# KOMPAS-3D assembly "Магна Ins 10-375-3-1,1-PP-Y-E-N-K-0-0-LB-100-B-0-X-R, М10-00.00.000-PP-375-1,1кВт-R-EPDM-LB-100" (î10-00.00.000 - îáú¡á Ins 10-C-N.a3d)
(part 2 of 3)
- Part/product: Магна Ins 10-425-3-1,1-PP-Y-E-N-K-0-0-L-0-B-0-X-M  | designation М10-00.00.000-PP-425-1,1кВт-M-EPDM
    Материал: Полипропилен  ГОСТ 26996-86 (density 900 kg/m3)
    Масса: 15.9855
  - Component [assembly]: Корпус полипропилен 425 1,1кВт  / с разъёмной муфтой  | designation М10-00.20.000-PP-425-1,1кВт-M  | pos. 2  | Материал: Полипропилен  ГОСТ 26996-86 (density 900 kg/m3); Масса: 5.90542; Раздел спецификации: Сборочные единицы; Форматы листов документа: 3xA3; Примечание: @100~)3xA3@101~)3xA3
  - Component [detail]: Электродвигатель / АИР 71B2 IM 3081 IP55 ф."Элком"  | pos. 14  | Масса: 8.3; Раздел спецификации: Прочие изделия; Примечание: См. заказ
  - Component [assembly]: Вал  | designation М10-00.15.000-1,1кВт-425  | pos. 1
      Материал: Полипропилен  ГОСТ 26996-86 (density 900 kg/m3)
      Масса: 0.906297
      Раздел спецификации: Сборочные единицы
      Форматы листов документа: 2xA3
      Примечание: @100~)2xA3
      source file: М10-00.15.000 - Вал.a3d
  - Component [detail]: Крышка  | designation М10-00.00.002  | pos. 4
      Материал: Полипропилен  ГОСТ 26996-86 (density 900 kg/m3)
      Масса: 0.324102
      Раздел спецификации: Детали
      Форматы листов документа: 4xA4
      Примечание: @100~)4xA4
      source file: М10-00.00.002 - Крышка.cdw, М10-00.00.002 - Крышка.m3d
  - Component [detail]: Импеллер Магна10  | designation М10-00.00.001  | pos. 3  | Масса: 0.169927; Раздел спецификации: Детали; Форматы листов документа: A3; source file: М10-00.00.001 - Импеллер Магна10.cdw, М10-00.00.001 - Импеллер Магна10.m3d
  - Component [detail]: Защитная втулка  | designation М10-00.00.003  | pos. 5  | Масса: 0.0193569; Раздел спецификации: Детали; Форматы листов документа: A4; source file: D:\Magna\Магна Ins\Магна ins 10\М10-00.00.000\3Д\М10-00.00.003 - Защитная втулка.cdw, М10-00.00.003 - Защитная втулка.m3d
  - Component [detail]: Втулка ответная  | designation М10А-00.00.003-01  | pos. 6  | Масса: 0.031838; Раздел спецификации: Детали; Форматы листов документа: A4; Примечание: Заим.; source file: D:\AquaProf\АкваProf 190\3Д модель\..\..\..\Magna\Магна Ins\Магна ins 10\М10-00.00.000\3Д\М10А-00.00.003-01 - Втулка ответная.cdw, D:\AquaProf\АкваProf 190\3Д модель\М10А-00.00.003 - Втулка ответная.m3d
  - Component [standard]: Шайба C.10.21 ГОСТ 11371-78  | qty 4  | pos. 11  | Материал: Сталь 12Х18Н10Т ГОСТ 5632-72 (density 1000 kg/m3); Масса: 0.003438; Раздел спецификации: Стандартные изделия; additional columns: C.8.21; Сталь 12Х18Н10Т ГОСТ 5632-72
  - Component [standard]: Шайба C.10.21 ГОСТ 11371-78  | qty 4  | pos. 11  | Материал: Сталь 12Х18Н10Т ГОСТ 5632-72 (density 1000 kg/m3); Масса: 0.003438; Раздел спецификации: Стандартные изделия; Рассекать на разрезах: no; additional columns: Сталь 12Х18Н10Т ГОСТ 5632-72
  - Component [standard]: Шайба 10 ГОСТ 6402-70  | qty 4  | pos. 10  | Масса: 0.00201; Раздел спецификации: Стандартные изделия; Примечание: Нерж.; Рассекать на разрезах: no; additional columns: 10; Без указания материала
  - Component [standard]: Гайка М10x1,25-6H(S16) ГОСТ 5915-70  | qty 4  | pos. 9  | Масса: 0.01022; Раздел спецификации: Стандартные изделия; Рассекать на разрезах: no; additional columns: М10x1,25-6H (S16); Сталь 12Х18Н10Т ГОСТ 5632-72
  - Component [standard]: Болт М10-6gx60.21.12Х18Н10Т ГОСТ 7798-70  | qty 4  | pos. 8  | Масса: 0.0467; Раздел спецификации: Стандартные изделия; additional columns: М8-6gx55.21.12Х18Н10Т; Сталь 12Х18Н10Т ГОСТ 5632-72
  - Component [detail]: Заглушка @2~25 FV PPR ф. "FV-Plast"  | qty 4  | pos. 12  | Материал: Полипропилен  ГОСТ 26996-86 (density 900 kg/m3); Масса: 0.0161976; Раздел спецификации: Прочие изделия
- Part/product: Магна Ins 10-425-3-0,75-PP-Y-E-N-K-0-0-L-0-B-0-X-R  | designation М10-00.00.000-PP-425-0,75кВт-R-EPDM
    Материал: Полипропилен  ГОСТ 26996-86 (density 900 kg/m3)
    Масса: 15.0715
  - Component [assembly]: Корпус полипропилен 425 0,75кВт  / с резьбовым переходником  | designation М10-00.20.000-PP-425-0,75кВт-R  | pos. 2  | Материал: Полипропилен  ГОСТ 26996-86 (density 900 kg/m3); Масса: 4.98891; Раздел спецификации: Сборочные единицы; Форматы листов документа: 3xA3; Примечание: @100~)3xA3@101~)3xA3
  - Component [assembly]: Вал  | designation М10-00.15.000-0,75кВт-425  | pos. 1
      Материал: Полипропилен  ГОСТ 26996-86 (density 900 kg/m3)
      Масса: 0.908797
      Раздел спецификации: Сборочные единицы
      Форматы листов документа: 2xA3
      Примечание: @100~)2xA3
      source file: М10-00.15.000 - Вал.a3d
  - Component [detail]: Крышка  | designation М10-00.00.002  | pos. 4
      Материал: Полипропилен  ГОСТ 26996-86 (density 900 kg/m3)
      Масса: 0.324102
      Раздел спецификации: Детали
      Форматы листов документа: 4xA4
      Примечание: @100~)4xA4
      source file: М10-00.00.002 - Крышка.cdw, М10-00.00.002 - Крышка.m3d
  - Component [detail]: Импеллер Магна10  | designation М10-00.00.001  | pos. 3  | Масса: 0.169927; Раздел спецификации: Детали; Форматы листов документа: A3; source file: М10-00.00.001 - Импеллер Магна10.cdw, М10-00.00.001 - Импеллер Магна10.m3d
  - Component [detail]: Защитная втулка  | designation М10-00.00.003  | pos. 5  | Масса: 0.0193569; Раздел спецификации: Детали; Форматы листов документа: A4; source file: D:\Magna\Магна Ins\Магна ins 10\М10-00.00.000\3Д\М10-00.00.003 - Защитная втулка.cdw, М10-00.00.003 - Защитная втулка.m3d
  - Component [detail]: Втулка ответная  | designation М10А-00.00.003-01  | pos. 6  | Масса: 0.031838; Раздел спецификации: Детали; Форматы листов документа: A4; Примечание: Заим.; source file: D:\AquaProf\АкваProf 190\3Д модель\..\..\..\Magna\Магна Ins\Магна ins 10\М10-00.00.000\3Д\М10А-00.00.003-01 - Втулка ответная.cdw, D:\AquaProf\АкваProf 190\3Д модель\М10А-00.00.003 - Втулка ответная.m3d
  - Component [standard]: Шайба C.10.21 ГОСТ 11371-78  | qty 4  | pos. 11  | Материал: Сталь 12Х18Н10Т ГОСТ 5632-72 (density 1000 kg/m3); Масса: 0.003438; Раздел спецификации: Стандартные изделия; additional columns: C.8.21; Сталь 12Х18Н10Т ГОСТ 5632-72
  - Component [standard]: Шайба C.10.21 ГОСТ 11371-78  | qty 4  | pos. 11  | Материал: Сталь 12Х18Н10Т ГОСТ 5632-72 (density 1000 kg/m3); Масса: 0.003438; Раздел спецификации: Стандартные изделия; Рассекать на разрезах: no; additional columns: Сталь 12Х18Н10Т ГОСТ 5632-72
  - Component [standard]: Шайба 10 ГОСТ 6402-70  | qty 4  | pos. 10  | Масса: 0.00201; Раздел спецификации: Стандартные изделия; Примечание: Нерж.; Рассекать на разрезах: no; additional columns: 10; Без указания материала
  - Component [standard]: Гайка М10x1,25-6H(S16) ГОСТ 5915-70  | qty 4  | pos. 9  | Масса: 0.01022; Раздел спецификации: Стандартные изделия; Рассекать на разрезах: no; additional columns: М10x1,25-6H (S16); Сталь 12Х18Н10Т ГОСТ 5632-72
  - Component [standard]: Болт М10-6gx60.21.12Х18Н10Т ГОСТ 7798-70  | qty 4  | pos. 8  | Масса: 0.0467; Раздел спецификации: Стандартные изделия; additional columns: М8-6gx55.21.12Х18Н10Т; Сталь 12Х18Н10Т ГОСТ 5632-72
  - Component [detail]: Заглушка @2~25 FV PPR ф. "FV-Plast"  | qty 4  | pos. 12  | Материал: Полипропилен  ГОСТ 26996-86 (density 900 kg/m3); Масса: 0.0161976; Раздел спецификации: Прочие изделия
- Part/product: Магна Ins 10-425-3-0,75-PP-Y-E-N-K-0-0-L-0-B-0-X-M  | designation М10-00.00.000-PP-425-0,75кВт-M-EPDM
    Материал: Полипропилен  ГОСТ 26996-86 (density 900 kg/m3)
    Масса: 15.988
  - Component [assembly]: Корпус полипропилен 425 0,75кВт  / с разъёмной муфтой  | designation М10-00.20.000-PP-425-0,75кВт-M  | pos. 2  | Материал: Полипропилен  ГОСТ 26996-86 (density 900 kg/m3); Масса: 5.90542; Раздел спецификации: Сборочные единицы; Форматы листов документа: 3xA3; Примечание: @100~)3xA3@101~)3xA3
  - Component [assembly]: Вал  | designation М10-00.15.000-0,75кВт-425  | pos. 1
      Материал: Полипропилен  ГОСТ 26996-86 (density 900 kg/m3)
      Масса: 0.908797
      Раздел спецификации: Сборочные единицы
      Форматы листов документа: 2xA3
      Примечание: @100~)2xA3
      source file: М10-00.15.000 - Вал.a3d
  - Component [detail]: Крышка  | designation М10-00.00.002  | pos. 4
      Материал: Полипропилен  ГОСТ 26996-86 (density 900 kg/m3)
      Масса: 0.324102
      Раздел спецификации: Детали
      Форматы листов документа: 4xA4
      Примечание: @100~)4xA4
      source file: М10-00.00.002 - Крышка.cdw, М10-00.00.002 - Крышка.m3d
  - Component [detail]: Импеллер Магна10  | designation М10-00.00.001  | pos. 3  | Масса: 0.169927; Раздел спецификации: Детали; Форматы листов документа: A3; source file: М10-00.00.001 - Импеллер Магна10.cdw, М10-00.00.001 - Импеллер Магна10.m3d
  - Component [detail]: Защитная втулка  | designation М10-00.00.003  | pos. 5  | Масса: 0.0193569; Раздел спецификации: Детали; Форматы листов документа: A4; source file: D:\Magna\Магна Ins\Магна ins 10\М10-00.00.000\3Д\М10-00.00.003 - Защитная втулка.cdw, М10-00.00.003 - Защитная втулка.m3d
  - Component [detail]: Втулка ответная  | designation М10А-00.00.003-01  | pos. 6  | Масса: 0.031838; Раздел спецификации: Детали; Форматы листов документа: A4; Примечание: Заим.; source file: D:\AquaProf\АкваProf 190\3Д модель\..\..\..\Magna\Магна Ins\Магна ins 10\М10-00.00.000\3Д\М10А-00.00.003-01 - Втулка ответная.cdw, D:\AquaProf\АкваProf 190\3Д модель\М10А-00.00.003 - Втулка ответная.m3d
  - Component [standard]: Шайба C.10.21 ГОСТ 11371-78  | qty 4  | pos. 11  | Материал: Сталь 12Х18Н10Т ГОСТ 5632-72 (density 1000 kg/m3); Масса: 0.003438; Раздел спецификации: Стандартные изделия; additional columns: C.8.21; Сталь 12Х18Н10Т ГОСТ 5632-72
  - Component [standard]: Шайба C.10.21 ГОСТ 11371-78  | qty 4  | pos. 11  | Материал: Сталь 12Х18Н10Т ГОСТ 5632-72 (density 1000 kg/m3); Масса: 0.003438; Раздел спецификации: Стандартные изделия; Рассекать на разрезах: no; additional columns: Сталь 12Х18Н10Т ГОСТ 5632-72
  - Component [standard]: Шайба 10 ГОСТ 6402-70  | qty 4  | pos. 10  | Масса: 0.00201; Раздел спецификации: Стандартные изделия; Примечание: Нерж.; Рассекать на разрезах: no; additional columns: 10; Без указания материала
  - Component [standard]: Гайка М10x1,25-6H(S16) ГОСТ 5915-70  | qty 4  | pos. 9  | Масса: 0.01022; Раздел спецификации: Стандартные изделия; Рассекать на разрезах: no; additional columns: М10x1,25-6H (S16); Сталь 12Х18Н10Т ГОСТ 5632-72
  - Component [standard]: Болт М10-6gx60.21.12Х18Н10Т ГОСТ 7798-70  | qty 4  | pos. 8  | Масса: 0.0467; Раздел спецификации: Стандартные изделия; additional columns: М8-6gx55.21.12Х18Н10Т; Сталь 12Х18Н10Т ГОСТ 5632-72
  - Component [detail]: Заглушка @2~25 FV PPR ф. "FV-Plast"  | qty 4  | pos. 12  | Материал: Полипропилен  ГОСТ 26996-86 (density 900 kg/m3); Масса: 0.0161976; Раздел спецификации: Прочие изделия
- Part/product: Магна Ins 10-PP-425-1,1кВт  | designation М10-00.00.000-PP-425-1,1кВт
    Материал: Полипропилен  ГОСТ 26996-86 (density 900 kg/m3)
    Масса: 15.0361
  - Component [detail]: Заглушка @2~25 FV PPR ф. "FV-Plast"  | qty 4  | pos. 12  | Материал: Полипропилен  ГОСТ 26996-86 (density 900 kg/m3); Масса: 0.0161976; Раздел спецификации: Прочие изделия
  - Component [standard]: Болт М10x1,25-6gx60 (S16) ГОСТ 7798-70  | qty 4  | pos. 8  | Масса: 0.0467; Раздел спецификации: Стандартные изделия; Рассекать на разрезах: no; additional columns: Сталь 12Х18Н10Т ГОСТ 5632-72
  - Component [standard]: Гайка М10x1,25-6H(S16) ГОСТ 5915-70  | qty 4  | pos. 9  | Масса: 0.01022; Раздел спецификации: Стандартные изделия; Рассекать на разрезах: no; additional columns: М10x1,25-6H (S16); Сталь 12Х18Н10Т ГОСТ 5632-72
  - Component [standard]: Шайба 10 ГОСТ 6402-70  | qty 4  | pos. 10  | Масса: 0.00201; Раздел спецификации: Стандартные изделия; Примечание: Нерж.; Рассекать на разрезах: no; additional columns: 10; Без указания материала
  - Component [standard]: Шайба C.10.21 ГОСТ 11371-78  | qty 8  | pos. 11  | Материал: Сталь 12Х18Н10Т ГОСТ 5632-72 (density 1000 kg/m3); Масса: 0.003438; Раздел спецификации: Стандартные изделия; Рассекать на разрезах: no; additional columns: Сталь 12Х18Н10Т ГОСТ 5632-72
  - Component [detail]: Втулка ответная  | designation М10А-00.00.003-01  | pos. 6  | Масса: 0.031838; Раздел спецификации: Детали; Форматы листов документа: A4; Примечание: Заим.; source file: D:\AquaProf\АкваProf 190\3Д модель\..\..\..\Magna\Магна Ins\Магна ins 10\М10-00.00.000\3Д\М10А-00.00.003-01 - Втулка ответная.cdw, D:\AquaProf\АкваProf 190\3Д модель\М10А-00.00.003 - Втулка ответная.m3d
  - Component [detail]: Защитная втулка  | designation М10-00.00.003  | pos. 5  | Масса: 0.0193569; Раздел спецификации: Детали; Форматы листов документа: A4; source file: D:\Magna\Магна Ins\Магна ins 10\М10-00.00.000\3Д\М10-00.00.003 - Защитная втулка.cdw, М10-00.00.003 - Защитная втулка.m3d
  - Component [detail]: Импеллер Магна10  | designation М10-00.00.001  | pos. 3  | Масса: 0.169927; Раздел спецификации: Детали; Форматы листов документа: A3; source file: М10-00.00.001 - Импеллер Магна10.cdw, М10-00.00.001 - Импеллер Магна10.m3d
  - Component [detail]: Крышка  | designation М10-00.00.002  | pos. 4
      Материал: Полипропилен  ГОСТ 26996-86 (density 900 kg/m3)
      Масса: 0.324102
      Раздел спецификации: Детали
      Форматы листов документа: 4xA4
      Примечание: @100~)4xA4
      source file: М10-00.00.002 - Крышка.cdw, М10-00.00.002 - Крышка.m3d
  - Component [assembly]: Вал  | designation М10-00.15.000-1,1кВт-425  | pos. 1
      Материал: Полипропилен  ГОСТ 26996-86 (density 900 kg/m3)
      Масса: 0.906297
      Раздел спецификации: Сборочные единицы
      Форматы листов документа: 2xA3
      Примечание: @100~)2xA3
      source file: М10-00.15.000 - Вал.a3d
  - Component [detail]: Электродвигатель / АИР 71B2 IM 3081 IP55 ф."Элком"  | pos. 14  | Масса: 8.3; Раздел спецификации: Прочие изделия; Примечание: См. заказ
  - Component [assembly]: Корпус полипропилен 425 1,1кВт  | designation М10-00.20.000-PP-425-1,1кВт  | pos. 2  | Материал: Полипропилен  ГОСТ 26996-86 (density 900 kg/m3); Масса: 4.95604; Раздел спецификации: Сборочные единицы; Форматы листов документа: 3xA3; Примечание: @100~)3xA3@101~)3xA3
- Part/product: Магна Ins 10-PP-425-0,75кВт  | designation М10-00.00.000-PP-425-0,75кВт
    Материал: Полипропилен  ГОСТ 26996-86 (density 900 kg/m3)
    Масса: 15.0386
  - Component [detail]: Заглушка @2~25 FV PPR ф. "FV-Plast"  | qty 4  | pos. 12  | Материал: Полипропилен  ГОСТ 26996-86 (density 900 kg/m3); Масса: 0.0161976; Раздел спецификации: Прочие изделия
  - Component [standard]: Болт М10x1,25-6gx60 (S16) ГОСТ 7798-70  | qty 4  | pos. 8  | Масса: 0.0467; Раздел спецификации: Стандартные изделия; Рассекать на разрезах: no; additional columns: Сталь 12Х18Н10Т ГОСТ 5632-72
  - Component [standard]: Гайка М10x1,25-6H(S16) ГОСТ 5915-70  | qty 4  | pos. 9  | Масса: 0.01022; Раздел спецификации: Стандартные изделия; Рассекать на разрезах: no; additional columns: М10x1,25-6H (S16); Сталь 12Х18Н10Т ГОСТ 5632-72
  - Component [standard]: Шайба 10 ГОСТ 6402-70  | qty 4  | pos. 10  | Масса: 0.00201; Раздел спецификации: Стандартные изделия; Примечание: Нерж.; Рассекать на разрезах: no; additional columns: 10; Без указания материала
  - Component [standard]: Шайба C.10.21 ГОСТ 11371-78  | qty 8  | pos. 11  | Материал: Сталь 12Х18Н10Т ГОСТ 5632-72 (density 1000 kg/m3); Масса: 0.003438; Раздел спецификации: Стандартные изделия; Рассекать на разрезах: no; additional columns: Сталь 12Х18Н10Т ГОСТ 5632-72
  - Component [detail]: Втулка ответная  | designation М10А-00.00.003-01  | pos. 6  | Масса: 0.031838; Раздел спецификации: Детали; Форматы листов документа: A4; Примечание: Заим.; source file: D:\AquaProf\АкваProf 190\3Д модель\..\..\..\Magna\Магна Ins\Магна ins 10\М10-00.00.000\3Д\М10А-00.00.003-01 - Втулка ответная.cdw, D:\AquaProf\АкваProf 190\3Д модель\М10А-00.00.003 - Втулка ответная.m3d
  - Component [detail]: Защитная втулка  | designation М10-00.00.003  | pos. 5  | Масса: 0.0193569; Раздел спецификации: Детали; Форматы листов документа: A4; source file: D:\Magna\Магна Ins\Магна ins 10\М10-00.00.000\3Д\М10-00.00.003 - Защитная втулка.cdw, М10-00.00.003 - Защитная втулка.m3d
  - Component [detail]: Импеллер Магна10  | designation М10-00.00.001  | pos. 3  | Масса: 0.169927; Раздел спецификации: Детали; Форматы листов документа: A3; source file: М10-00.00.001 - Импеллер Магна10.cdw, М10-00.00.001 - Импеллер Магна10.m3d
  - Component [detail]: Крышка  | designation М10-00.00.002  | pos. 4
      Материал: Полипропилен  ГОСТ 26996-86 (density 900 kg/m3)
      Масса: 0.324102
      Раздел спецификации: Детали
      Форматы листов документа: 4xA4
      Примечание: @100~)4xA4
      source file: М10-00.00.002 - Крышка.cdw, М10-00.00.002 - Крышка.m3d
  - Component [assembly]: Вал  | designation М10-00.15.000-0,75кВт-425  | pos. 1
      Материал: Полипропилен  ГОСТ 26996-86 (density 900 kg/m3)
      Масса: 0.908797
      Раздел спецификации: Сборочные единицы
      Форматы листов документа: 2xA3
      Примечание: @100~)2xA3
      source file: М10-00.15.000 - Вал.a3d
  - Component [assembly]: Корпус полипропилен 425 0,75кВт  | designation М10-00.20.000-PP-425-0,75кВт  | pos. 2  | Материал: Полипропилен  ГОСТ 26996-86 (density 900 kg/m3); Масса: 4.95604; Раздел спецификации: Сборочные единицы; Форматы листов документа: 3xA3; Примечание: @100~)3xA3@101~)3xA3
- Part/product: Магна Ins 10-PP-475  | designation М10-00.00.000-PP-475
    Материал: Полипропилен  ГОСТ 26996-86 (density 900 kg/m3)
    Масса: 11.8893
  - Component [assembly]: Корпус полипропилен  | designation М10-00.20.000-PP-475  | pos. 2  | Материал: Полипропилен  ГОСТ 26996-86 (density 900 kg/m3); Масса: 5.45783; Раздел спецификации: Сборочные единицы; Форматы листов документа: 3xA3; Примечание: @100~)3xA3@101~)3xA3
  - Component [assembly]: Вал  | designation М10-00.15.000-0,55кВт-475  | pos. 1
      Материал: Полипропилен  ГОСТ 26996-86 (density 900 kg/m3)
      Масса: 0.642468
      Раздел спецификации: Сборочные единицы
      Форматы листов документа: 2xA3
      Примечание: @100~)2xA3
      source file: М10-00.15.000 - Вал.a3d
  - Component [detail]: Крышка  | designation М10-00.00.002  | pos. 4
      Материал: Полипропилен  ГОСТ 26996-86 (density 900 kg/m3)
      Масса: 0.324102
      Раздел спецификации: Детали
      Форматы листов документа: 4xA4
      Примечание: @100~)4xA4
      source file: М10-00.00.002 - Крышка.cdw, М10-00.00.002 - Крышка.m3d
  - Component [detail]: Импеллер Магна10  | designation М10-00.00.001  | pos. 3  | Масса: 0.169927; Раздел спецификации: Детали; Форматы листов документа: A3; source file: М10-00.00.001 - Импеллер Магна10.cdw, М10-00.00.001 - Импеллер Магна10.m3d
  - Component [detail]: Защитная втулка  | designation М10-00.00.003  | pos. 5  | Масса: 0.0193569; Раздел спецификации: Детали; Форматы листов документа: A4; source file: D:\Magna\Магна Ins\Магна ins 10\М10-00.00.000\3Д\М10-00.00.003 - Защитная втулка.cdw, М10-00.00.003 - Защитная втулка.m3d
  - Component [detail]: Втулка ответная  | designation М10А-00.00.003-01  | pos. 6  | Масса: 0.031838; Раздел спецификации: Детали; Форматы листов документа: A4; Примечание: Заим.; source file: D:\AquaProf\АкваProf 190\3Д модель\..\..\..\Magna\Магна Ins\Магна ins 10\М10-00.00.000\3Д\М10А-00.00.003-01 - Втулка ответная.cdw, D:\AquaProf\АкваProf 190\3Д модель\М10А-00.00.003 - Втулка ответная.m3d
- Part/product: Магна Ins 10-PP-375-1,1кВт  | designation М10-00.00.000-PP-375-1,1кВт
    Материал: Полипропилен  ГОСТ 26996-86 (density 900 kg/m3)
    Масса: 14.4037
  - Component [detail]: Заглушка @2~25 FV PPR ф. "FV-Plast"  | qty 4  | pos. 12  | Материал: Полипропилен  ГОСТ 26996-86 (density 900 kg/m3); Масса: 0.0161976; Раздел спецификации: Прочие изделия
  - Component [standard]: Болт М10x1,25-6gx60 (S16) ГОСТ 7798-70  | qty 4  | pos. 8  | Масса: 0.0467; Раздел спецификации: Стандартные изделия; Рассекать на разрезах: no; additional columns: Сталь 12Х18Н10Т ГОСТ 5632-72
  - Component [standard]: Гайка М10x1,25-6H(S16) ГОСТ 5915-70  | qty 4  | pos. 9  | Масса: 0.01022; Раздел спецификации: Стандартные изделия; Рассекать на разрезах: no; additional columns: М10x1,25-6H (S16); Сталь 12Х18Н10Т ГОСТ 5632-72
  - Component [standard]: Шайба 10 ГОСТ 6402-70  | qty 4  | pos. 10  | Масса: 0.00201; Раздел спецификации: Стандартные изделия; Примечание: Нерж.; Рассекать на разрезах: no; additional columns: 10; Без указания материала
  - Component [standard]: Шайба C.10.21 ГОСТ 11371-78  | qty 8  | pos. 11  | Материал: Сталь 12Х18Н10Т ГОСТ 5632-72 (density 1000 kg/m3); Масса: 0.003438; Раздел спецификации: Стандартные изделия; Рассекать на разрезах: no; additional columns: Сталь 12Х18Н10Т ГОСТ 5632-72
  - Component [detail]: Втулка ответная  | designation М10А-00.00.003-01  | pos. 6  | Масса: 0.031838; Раздел спецификации: Детали; Форматы листов документа: A4; Примечание: Заим.; source file: D:\AquaProf\АкваProf 190\3Д модель\..\..\..\Magna\Магна Ins\Магна ins 10\М10-00.00.000\3Д\М10А-00.00.003-01 - Втулка ответная.cdw, D:\AquaProf\АкваProf 190\3Д модель\М10А-00.00.003 - Втулка ответная.m3d
  - Component [detail]: Защитная втулка  | designation М10-00.00.003  | pos. 5  | Масса: 0.0193569; Раздел спецификации: Детали; Форматы листов документа: A4; source file: D:\Magna\Магна Ins\Магна ins 10\М10-00.00.000\3Д\М10-00.00.003 - Защитная втулка.cdw, М10-00.00.003 - Защитная втулка.m3d
  - Component [detail]: Импеллер Магна10  | designation М10-00.00.001  | pos. 3  | Масса: 0.169927; Раздел спецификации: Детали; Форматы листов документа: A3; source file: М10-00.00.001 - Импеллер Магна10.cdw, М10-00.00.001 - Импеллер Магна10.m3d
  - Component [detail]: Крышка  | designation М10-00.00.002  | pos. 4
      Материал: Полипропилен  ГОСТ 26996-86 (density 900 kg/m3)
      Масса: 0.324102
      Раздел спецификации: Детали
      Форматы листов документа: 4xA4
      Примечание: @100~)4xA4
      source file: М10-00.00.002 - Крышка.cdw, М10-00.00.002 - Крышка.m3d
  - Component [assembly]: Вал  | designation М10-00.15.000  | pos. 1
      Материал: Полипропилен  ГОСТ 26996-86 (density 900 kg/m3)
      Масса: 0.519317
      Раздел спецификации: Сборочные единицы
      Форматы листов документа: 2xA3
      Примечание: @100~)2xA3
      source file: М10-00.15.000 - Вал.a3d, М10-00.15.000 - Вал.cdw
  - Component [detail]: Электродвигатель / АИР 71B2 IM 3081 IP55 ф."Элком"  | pos. 14  | Масса: 8.3; Раздел спецификации: Прочие изделия; Примечание: См. заказ
- Part/product: Магна Ins 10-375-3-0,55-PP-Y-E-N-K-0-0-L-0-B-0-X-R  | designation М10-00.00.000-PP-375-0,55кВт-R-EPDM
    Материал: Полипропилен  ГОСТ 26996-86 (density 900 kg/m3)
    Масса: 11.3082
  - Component [detail]: Кольцо уплотнительное плоское 10-18-25  | designation EPDM  | pos. 93  | Масса: 0.000562973; Раздел спецификации: Прочие изделия; source file: Кольцо уплотнительное плоское 10-18-25 ЕPDM.m3d
  - Component [assembly]: Корпус полипропилен 375 0,55 кВт  / с резьбовым переходником  | designation М10-00.20.000-PP-375-0,55кВт-R  | pos. 2
      Материал: Полипропилен  ГОСТ 26996-86 (density 900 kg/m3)
      Масса: 4.99986
      Раздел спецификации: Сборочные единицы
      Форматы листов документа: 3xA3
      Примечание: @100~)3xA3@101~)3xA3
      source file: М10-00.20.000 - Корпус.a3d
  - Component [assembly]: Вал  | designation М10-00.15.000-0,55кВт-375  | pos. 1
      Материал: Полипропилен  ГОСТ 26996-86 (density 900 kg/m3)
      Масса: 0.519317
      Раздел спецификации: Сборочные единицы
      Форматы листов документа: 2xA3
      Примечание: @100~)2xA3
      source file: М10-00.15.000 - Вал.a3d
  - Component [detail]: Крышка  | designation М10-00.00.002  | pos. 4
      Материал: Полипропилен  ГОСТ 26996-86 (density 900 kg/m3)
      Масса: 0.324102
      Раздел спецификации: Детали
      Форматы листов документа: 4xA4
      Примечание: @100~)4xA4
      source file: М10-00.00.002 - Крышка.cdw, М10-00.00.002 - Крышка.m3d
  - Component [detail]: Импеллер Магна10  | designation М10-00.00.001  | pos. 3  | Масса: 0.169927; Раздел спецификации: Детали; Форматы листов документа: A3; source file: М10-00.00.001 - Импеллер Магна10.cdw, М10-00.00.001 - Импеллер Магна10.m3d
  - Component [detail]: Защитная втулка  | designation М10-00.00.003  | pos. 5  | Масса: 0.0193569; Раздел спецификации: Детали; Форматы листов документа: A4; source file: D:\Magna\Магна Ins\Магна ins 10\М10-00.00.000\3Д\М10-00.00.003 - Защитная втулка.cdw, М10-00.00.003 - Защитная втулка.m3d
  - Component [detail]: Втулка ответная  | designation М10А-00.00.003-01  | pos. 6  | Масса: 0.031838; Раздел спецификации: Детали; Форматы листов документа: A4; Примечание: Заим.; source file: D:\AquaProf\АкваProf 190\3Д модель\..\..\..\Magna\Магна Ins\Магна ins 10\М10-00.00.000\3Д\М10А-00.00.003-01 - Втулка ответная.cdw, D:\AquaProf\АкваProf 190\3Д модель\М10А-00.00.003 - Втулка ответная.m3d
  - Component [detail]: Заглушка @2~20 FV PPR ф. "FV-Plast"  | pos. 12  | Масса: 0.0187746; Раздел спецификации: Прочие изделия; source file: Заглушка ф20 FV PPR ф. FV-Plast.m3d
  - Component [detail]: Электродвигатель АИР 63В2 / IM 3081 0,55кВт 3000 об/мин  | pos. 14  | Масса: 5.02; Раздел спецификации: Прочие изделия; Примечание: IP55; source file: Электродвигатель АИР 63В2 IM 3081 0,55кВт 3000 об..m3d
- Part/product: Магна Ins 10-PP-375-0,55кВт  | designation М10-00.00.000-PP-375-0,55кВт
    Материал: Полипропилен  ГОСТ 26996-86 (density 900 kg/m3)
    Масса: 11.2753
  - Component [detail]: Втулка ответная  | designation М10А-00.00.003-01  | pos. 6  | Масса: 0.031838; Раздел спецификации: Детали; Форматы листов документа: A4; Примечание: Заим.; source file: D:\AquaProf\АкваProf 190\3Д модель\..\..\..\Magna\Магна Ins\Магна ins 10\М10-00.00.000\3Д\М10А-00.00.003-01 - Втулка ответная.cdw, D:\AquaProf\АкваProf 190\3Д модель\М10А-00.00.003 - Втулка ответная.m3d
  - Component [detail]: Защитная втулка  | designation М10-00.00.003  | pos. 5  | Масса: 0.0193569; Раздел спецификации: Детали; Форматы листов документа: A4; source file: D:\Magna\Магна Ins\Магна ins 10\М10-00.00.000\3Д\М10-00.00.003 - Защитная втулка.cdw, М10-00.00.003 - Защитная втулка.m3d
  - Component [detail]: Импеллер Магна10  | designation М10-00.00.001  | pos. 3  | Масса: 0.169927; Раздел спецификации: Детали; Форматы листов документа: A3; source file: М10-00.00.001 - Импеллер Магна10.cdw, М10-00.00.001 - Импеллер Магна10.m3d
  - Component [detail]: Крышка  | designation М10-00.00.002  | pos. 4
      Материал: Полипропилен  ГОСТ 26996-86 (density 900 kg/m3)
      Масса: 0.324102
      Раздел спецификации: Детали
      Форматы листов документа: 4xA4
      Примечание: @100~)4xA4
      source file: М10-00.00.002 - Крышка.cdw, М10-00.00.002 - Крышка.m3d
  - Component [assembly]: Вал  | designation М10-00.15.000-0,55кВт-375  | pos. 1
      Материал: Полипропилен  ГОСТ 26996-86 (density 900 kg/m3)
      Масса: 0.519317
      Раздел спецификации: Сборочные единицы
      Форматы листов документа: 2xA3
      Примечание: @100~)2xA3
      source file: М10-00.15.000 - Вал.a3d
  - Component [assembly]: Корпус полипропилен 375 0,55 кВт  | designation М10-00.20.000-PP-375-0,55кВт  | pos. 2  | Материал: Полипропилен  ГОСТ 26996-86 (density 900 kg/m3); Масса: 4.96698; Раздел спецификации: Сборочные единицы; Форматы листов документа: 3xA3; Примечание: @100~)3xA3@101~)3xA3
  - Component [detail]: Электродвигатель АИР 63В2 / IM 3081 0,55кВт 3000 об/мин  | pos. 321  | Масса: 5.02; Раздел спецификации: Прочие изделия; Примечание: IP55; source file: Электродвигатель АИР 63В2 IM 3081 0,55кВт 3000 об..m3d
- Part/product: Магна Ins 10-PP-375  | designation М10-00.00.000-PP-375
    Материал: Полипропилен  ГОСТ 26996-86 (density 900 kg/m3)
    Масса: 11.2753
  - Component [assembly]: Вал  | designation М10-00.15.000  | pos. 1
      Материал: Полипропилен  ГОСТ 26996-86 (density 900 kg/m3)
      Масса: 0.519317
      Раздел спецификации: Сборочные единицы
      Форматы листов документа: 2xA3
      Примечание: @100~)2xA3
      source file: М10-00.15.000 - Вал.a3d, М10-00.15.000 - Вал.cdw
  - Component [detail]: Крышка  | designation М10-00.00.002  | pos. 4
      Материал: Полипропилен  ГОСТ 26996-86 (density 900 kg/m3)
      Масса: 0.324102
      Раздел спецификации: Детали
      Форматы листов документа: 4xA4
      Примечание: @100~)4xA4
      source file: М10-00.00.002 - Крышка.cdw, М10-00.00.002 - Крышка.m3d
  - Component [detail]: Импеллер Магна10  | designation М10-00.00.001  | pos. 3  | Масса: 0.169927; Раздел спецификации: Детали; Форматы листов документа: A3; source file: М10-00.00.001 - Импеллер Магна10.cdw, М10-00.00.001 - Импеллер Магна10.m3d
  - Component [detail]: Защитная втулка  | designation М10-00.00.003  | pos. 5  | Масса: 0.0193569; Раздел спецификации: Детали; Форматы листов документа: A4; source file: D:\Magna\Магна Ins\Магна ins 10\М10-00.00.000\3Д\М10-00.00.003 - Защитная втулка.cdw, М10-00.00.003 - Защитная втулка.m3d
  - Component [detail]: Втулка ответная  | designation М10А-00.00.003-01  | pos. 6  | Масса: 0.031838; Раздел спецификации: Детали; Форматы листов документа: A4; Примечание: Заим.; source file: D:\AquaProf\АкваProf 190\3Д модель\..\..\..\Magna\Магна Ins\Магна ins 10\М10-00.00.000\3Д\М10А-00.00.003-01 - Втулка ответная.cdw, D:\AquaProf\АкваProf 190\3Д модель\М10А-00.00.003 - Втулка ответная.m3d
- Part/product: Магна Ins 10-PP  | designation М10-00.00.000-PP
    Материал: Полипропилен  ГОСТ 26996-86 (density 900 kg/m3)
    Масса: 11.2753
  - Component [detail]: Втулка ответная  | designation М10А-00.00.003-01  | pos. 6  | Масса: 0.031838; Раздел спецификации: Детали; Форматы листов документа: A4; Примечание: Заим.; source file: D:\AquaProf\АкваProf 190\3Д модель\М10А-00.00.003 - Втулка ответная.m3d, М10А-00.00.003-01 - Втулка ответная.cdw
  - Component [detail]: Защитная втулка  | designation М10-00.00.003  | pos. 5  | Масса: 0.0193569; Раздел спецификации: Детали; Форматы листов документа: A4; source file: D:\Magna\Магна Ins\Магна ins 10\М10-00.00.000\3Д\М10-00.00.003 - Защитная втулка.cdw, М10-00.00.003 - Защитная втулка.m3d
  - Component [detail]: Крышка  | designation М10-00.00.002  | pos. 4
      Материал: Полипропилен  ГОСТ 26996-86 (density 900 kg/m3)
      Масса: 0.324102
      Раздел спецификации: Детали
      Форматы листов документа: 4xA4
      Примечание: @100~)4xA4
      source file: М10-00.00.002 - Крышка.cdw, М10-00.00.002 - Крышка.m3d
  - Component [assembly]: Вал  | designation М10-00.15.000  | pos. 1
      Материал: Полипропилен  ГОСТ 26996-86 (density 900 kg/m3)
      Масса: 0.519317
      Раздел спецификации: Сборочные единицы
      Форматы листов документа: 2xA3
      Примечание: @100~)2xA3
      source file: М10-00.15.000 - Вал.a3d, М10-00.15.000 - Вал.cdw
- Part/product: Магна Ins 10-C-N  | designation М10-00.00.000
    Материал: Полипропилен  ГОСТ 26996-86 (density 900 kg/m3)
    Масса: 11.2753
    source file: М10-00.00.000 - Магна Ins 10-C-N.cdw
  - Component [detail]: Кольцо уплотнительное плоское 10-18-25  | designation EPDM  | pos. 93  | Масса: 0.000562973; Раздел спецификации: Прочие изделия; source file: Кольцо уплотнительное плоское 10-18-25 ЕPDM.m3d
  - Component [assembly]: Корпус  | designation М10-00.20.000  | pos. 2
      Материал: Полипропилен  ГОСТ 26996-86 (density 900 kg/m3)
      Масса: 4.96698
      Раздел спецификации: Сборочные единицы
      Форматы листов документа: 3xA3
      Примечание: @100~)3xA3@101~)3xA3
      source file: М10-00.20.000 - Корпус.a3d, М10-00.20.000 - Корпус.cdw
  - Component [detail]: Электродвигатель АИР 63В2 / IM 3081 0,55кВт 3000 об/мин  | pos. 14  | Масса: 5.02; Раздел спецификации: Прочие изделия; Примечание: См. заказ; source file: Электродвигатель АИР 63В2 IM 3081 0,55кВт 3000 об..m3d
  - Component [assembly]: Вал  | designation М10-00.15.000  | pos. 1
      Материал: Полипропилен  ГОСТ 26996-86 (density 900 kg/m3)
      Масса: 0.519317
      Раздел спецификации: Сборочные единицы
      Форматы листов документа: 2xA3
      Примечание: @100~)2xA3
      source file: М10-00.15.000 - Вал.a3d, М10-00.15.000 - Вал.cdw
  - Component [detail]: Крышка  | designation М10-00.00.002  | pos. 4
      Материал: Полипропилен  ГОСТ 26996-86 (density 900 kg/m3)
      Масса: 0.324102
      Раздел спецификации: Детали
      Форматы листов документа: 4xA4
      Примечание: @100~)4xA4
      source file: М10-00.00.002 - Крышка.cdw, М10-00.00.002 - Крышка.m3d
  - Component [detail]: Импеллер Магна10  | designation М10-00.00.001  | pos. 3  | Масса: 0.169927; Раздел спецификации: Детали; Форматы листов документа: A3; source file: М10-00.00.001 - Импеллер Магна10.cdw, М10-00.00.001 - Импеллер Магна10.m3d
  - Component [detail]: Защитная втулка  | designation М10-00.00.003  | pos. 5  | Масса: 0.0193569; Раздел спецификации: Детали; Форматы листов документа: A4; source file: D:\Magna\Магна Ins\Магна ins 10\М10-00.00.000\3Д\М10-00.00.003 - Защитная втулка.cdw, М10-00.00.003 - Защитная втулка.cdw, М10-00.00.003 - Защитная втулка.m3d
  - Component [detail]: Втулка ответная  | designation М10А-00.00.003-01  | pos. 6  | Масса: 0.031838; Раздел спецификации: Детали; Форматы листов документа: A4; Примечание: Заим.; source file: D:\AquaProf\АкваProf 190\3Д модель\М10А-00.00.003 - Втулка ответная.m3d, М10А-00.00.003-01 - Втулка ответная.cdw
  - Component [standard]: Шайба C.8.21 ГОСТ 11371-78  | qty 8  | pos. 11  | Материал: Сталь 12Х18Н10Т ГОСТ 5632-72 (density 1000 kg/m3); Масса: 0.001725; Раздел спецификации: Стандартные изделия; additional columns: Сталь 12Х18Н10Т ГОСТ 5632-72; source file: ..\..\..\..\Program Files\ASCON\KOMPAS-3D v18\Libs\PartLib\DATA\VAULT\methods\kompas\3d\PLib_Washer_1_712.m3d
  - Component [standard]: Шайба 8 ГОСТ 6402-70  | qty 4  | pos. 10  | Масса: 0.001034; Раздел спецификации: Стандартные изделия; Примечание: Нерж.; additional columns: 8; Без указания материала; source file: ..\..\..\..\Program Files\ASCON\KOMPAS-3D v18\Libs\PartLib\DATA\VAULT\methods\kompas\3d\PLib_Washer_2_712.m3d
  - Component [standard]: Гайка М8-6H.21.12Х18Н10Т ГОСТ 5915-70  | qty 4  | pos. 9  | Материал: Сталь 12Х18Н10Т ГОСТ 5632-72 (density 1000 kg/m3); Масса: 0.005548; Раздел спецификации: Стандартные изделия; additional columns: Сталь 12Х18Н10Т ГОСТ 5632-72; source file: ..\..\..\..\Program Files\ASCON\KOMPAS-3D v18\Libs\PartLib\DATA\VAULT\methods\kompas\3d\PLib_Nut_OST92_900.m3d
  - Component [standard]: Болт М8-6gx55.21.12Х18Н10Т ГОСТ 7798-70  | qty 4  | pos. 8  | Материал: Сталь 12Х18Н10Т ГОСТ 5632-72 (density 1000 kg/m3); Масса: 0.02699; Раздел спецификации: Стандартные изделия; additional columns: Сталь 12Х18Н10Т ГОСТ 5632-72; source file: ..\..\..\..\Program Files\ASCON\KOMPAS-3D v18\Libs\PartLib\DATA\VAULT\methods\kompas\3d\PLib_Bolt_1_900.m3d
  - Component [detail]: Заглушка @2~20 FV PPR ф. "FV-Plast"  | qty 4  | pos. 12  | Масса: 0.0187746; Раздел спецификации: Прочие изделия; source file: Заглушка ф20 FV PPR ф. FV-Plast.m3d
  - Component: Шайба C.10.21 ГОСТ 11371-78  | pos. 11  | Материал: Сталь 12Х18Н10Т ГОСТ 5632-72; Масса: 0.0034; Раздел спецификации: Стандартные изделия
- Part/product: Магна Ins 10-375-3-0,55-PP-Y-E-N-K-0-0-L-0-B-0-X-M  | designation М10-00.00.000-PP-375-0,55кВт-M-EPDM
    Материал: Полипропилен  ГОСТ 26996-86 (density 900 kg/m3)
    Масса: 12.2247
  - Component [assembly]: Корпус полипропилен 375 0,55 кВт  / с разъёмной муфтой  | designation М10-00.20.000-PP-375-0,55кВт-M  | pos. 2
      Материал: Полипропилен  ГОСТ 26996-86 (density 900 kg/m3)
      Масса: 5.91637
      Раздел спецификации: Сборочные единицы
      Форматы листов документа: 3xA3
      Примечание: @100~)3xA3@101~)3xA3
      source file: М10-00.20.000 - Корпус.a3d
  - Component [assembly]: Вал  | designation М10-00.15.000-0,55кВт-375  | pos. 1
      Материал: Полипропилен  ГОСТ 26996-86 (density 900 kg/m3)
      Масса: 0.519317
      Раздел спецификации: Сборочные единицы
      Форматы листов документа: 2xA3
      Примечание: @100~)2xA3
      source file: М10-00.15.000 - Вал.a3d
  - Component [detail]: Крышка  | designation М10-00.00.002  | pos. 4
      Материал: Полипропилен  ГОСТ 26996-86 (density 900 kg/m3)
      Масса: 0.324102
      Раздел спецификации: Детали
      Форматы листов документа: 4xA4
      Примечание: @100~)4xA4
      source file: М10-00.00.002 - Крышка.cdw, М10-00.00.002 - Крышка.m3d
  - Component [detail]: Импеллер Магна10  | designation М10-00.00.001  | pos. 3  | Масса: 0.169927; Раздел спецификации: Детали; Форматы листов документа: A3; source file: М10-00.00.001 - Импеллер Магна10.cdw, М10-00.00.001 - Импеллер Магна10.m3d
  - Component [detail]: Защитная втулка  | designation М10-00.00.003  | pos. 5  | Масса: 0.0193569; Раздел спецификации: Детали; Форматы листов документа: A4; source file: D:\Magna\Магна Ins\Магна ins 10\М10-00.00.000\3Д\М10-00.00.003 - Защитная втулка.cdw, М10-00.00.003 - Защитная втулка.m3d
  - Component [detail]: Втулка ответная  | designation М10А-00.00.003-01  | pos. 6  | Масса: 0.031838; Раздел спецификации: Детали; Форматы листов документа: A4; Примечание: Заим.; source file: D:\AquaProf\АкваProf 190\3Д модель\..\..\..\Magna\Магна Ins\Магна ins 10\М10-00.00.000\3Д\М10А-00.00.003-01 - Втулка ответная.cdw, D:\AquaProf\АкваProf 190\3Д модель\М10А-00.00.003 - Втулка ответная.m3d
  - Component [detail]: Электродвигатель АИР 63В2 / IM 3081 0,55кВт 3000 об/мин  | pos. 321  | Масса: 5.02; Раздел спецификации: Прочие изделия; Примечание: IP55; source file: Электродвигатель АИР 63В2 IM 3081 0,55кВт 3000 об..m3d
- Part/product: Магна Ins 10-PP-375-0,75кВт  | designation М10-00.00.000-PP-375-0,75кВт
    Материал: Полипропилен  ГОСТ 26996-86 (density 900 kg/m3)
    Масса: 14.6914
  - Component [detail]: Заглушка @2~25 FV PPR ф. "FV-Plast"  | qty 4  | pos. 12  | Материал: Полипропилен  ГОСТ 26996-86 (density 900 kg/m3); Масса: 0.0161976; Раздел спецификации: Прочие изделия
  - Component [standard]: Болт М10x1,25-6gx60 (S16) ГОСТ 7798-70  | qty 4  | pos. 8  | Масса: 0.0467; Раздел спецификации: Стандартные изделия; Рассекать на разрезах: no; additional columns: Сталь 12Х18Н10Т ГОСТ 5632-72
  - Component [standard]: Гайка М10x1,25-6H(S16) ГОСТ 5915-70  | qty 4  | pos. 9  | Масса: 0.01022; Раздел спецификации: Стандартные изделия; Рассекать на разрезах: no; additional columns: М10x1,25-6H (S16); Сталь 12Х18Н10Т ГОСТ 5632-72
  - Component [standard]: Шайба 10 ГОСТ 6402-70  | qty 4  | pos. 10  | Масса: 0.00201; Раздел спецификации: Стандартные изделия; Примечание: Нерж.; Рассекать на разрезах: no; additional columns: 10; Без указания материала
  - Component [standard]: Шайба C.10.21 ГОСТ 11371-78  | qty 8  | pos. 11  | Материал: Сталь 12Х18Н10Т ГОСТ 5632-72 (density 1000 kg/m3); Масса: 0.003438; Раздел спецификации: Стандартные изделия; Рассекать на разрезах: no; additional columns: Сталь 12Х18Н10Т ГОСТ 5632-72
  - Component [detail]: Втулка ответная  | designation М10А-00.00.003-01  | pos. 6  | Масса: 0.031838; Раздел спецификации: Детали; Форматы листов документа: A4; Примечание: Заим.; source file: D:\AquaProf\АкваProf 190\3Д модель\..\..\..\Magna\Магна Ins\Магна ins 10\М10-00.00.000\3Д\М10А-00.00.003-01 - Втулка ответная.cdw, D:\AquaProf\АкваProf 190\3Д модель\М10А-00.00.003 - Втулка ответная.m3d
  - Component [detail]: Защитная втулка  | designation М10-00.00.003  | pos. 5  | Масса: 0.0193569; Раздел спецификации: Детали; Форматы листов документа: A4; source file: D:\Magna\Магна Ins\Магна ins 10\М10-00.00.000\3Д\М10-00.00.003 - Защитная втулка.cdw, М10-00.00.003 - Защитная втулка.m3d
  - Component [detail]: Импеллер Магна10  | designation М10-00.00.001  | pos. 3  | Масса: 0.169927; Раздел спецификации: Детали; Форматы листов документа: A3; source file: М10-00.00.001 - Импеллер Магна10.cdw, М10-00.00.001 - Импеллер Магна10.m3d
  - Component [detail]: Крышка  | designation М10-00.00.002  | pos. 4
      Материал: Полипропилен  ГОСТ 26996-86 (density 900 kg/m3)
      Масса: 0.324102
      Раздел спецификации: Детали
      Форматы листов документа: 4xA4
      Примечание: @100~)4xA4
      source file: М10-00.00.002 - Крышка.cdw, М10-00.00.002 - Крышка.m3d
  - Component [assembly]: Вал  | designation М10-00.15.000-0,75кВт  | pos. 1  | Материал: Полипропилен  ГОСТ 26996-86 (density 900 kg/m3); Масса: 0.807009; Раздел спецификации: Сборочные единицы; Форматы листов документа: 2xA3; Примечание: @100~)2xA3
  - Component [assembly]: Корпус полипропилен 375 0,75кВт  | designation М10-00.20.000-PP-375-0,75кВт  | pos. 2  | Материал: Полипропилен  ГОСТ 26996-86 (density 900 kg/m3); Масса: 4.71061; Раздел спецификации: Сборочные единицы; Форматы листов документа: 3xA3; Примечание: @100~)3xA3@101~)3xA3
  - Component [detail]: Электродвигатель 3ф. АИР 71А2 / 380В 0,75кВт 3000 об/мин 3081 DRIVE IEK / арт.DRV071-A2-000-8-3030  | pos. 356  | Масса: 8.3; Раздел спецификации: Прочие изделия; Примечание: IP55; source file: Электродвигатель 3ф. АИР 71А2 380В 0,75кВт 3000об_мин 3081 DRIVE IEK.m3d
- Part/product: Магна Ins 10-375-3-0,75-PP-Y-E-N-K-0-0-L-0-B-0-X-M  | designation М10-00.00.000-PP-375-0,75кВт-M-EPDM
    Материал: Полипропилен  ГОСТ 26996-86 (density 900 kg/m3)
    Масса: 15.6408
  - Component [assembly]: Корпус полипропилен 375 0,75кВт  / с разъёмной муфтой  | designation М10-00.20.000-PP-375-0,75кВт-M  | pos. 2
      Материал: Полипропилен  ГОСТ 26996-86 (density 900 kg/m3)
      Масса: 5.65999
      Раздел спецификации: Сборочные единицы
      Форматы листов документа: 3xA3
      Примечание: @100~)3xA3@101~)3xA3
      source file: М10-00.20.000 - Корпус.a3d
  - Component [assembly]: Вал  | designation М10-00.15.000-0,75кВт-375  | pos. 1
      Материал: Полипропилен  ГОСТ 26996-86 (density 900 kg/m3)
      Масса: 0.807009
      Раздел спецификации: Сборочные единицы
      Форматы листов документа: 2xA3
      Примечание: @100~)2xA3
      source file: М10-00.15.000 - Вал.a3d
  - Component [detail]: Крышка  | designation М10-00.00.002  | pos. 4
      Материал: Полипропилен  ГОСТ 26996-86 (density 900 kg/m3)
      Масса: 0.324102
      Раздел спецификации: Детали
      Форматы листов документа: 4xA4
      Примечание: @100~)4xA4
      source file: М10-00.00.002 - Крышка.cdw, М10-00.00.002 - Крышка.m3d
  - Component [detail]: Импеллер Магна10  | designation М10-00.00.001  | pos. 3  | Масса: 0.169927; Раздел спецификации: Детали; Форматы листов документа: A3; source file: М10-00.00.001 - Импеллер Магна10.cdw, М10-00.00.001 - Импеллер Магна10.m3d
  - Component [detail]: Защитная втулка  | designation М10-00.00.003  | pos. 5  | Масса: 0.0193569; Раздел спецификации: Детали; Форматы листов документа: A4; source file: D:\Magna\Магна Ins\Магна ins 10\М10-00.00.000\3Д\М10-00.00.003 - Защитная втулка.cdw, М10-00.00.003 - Защитная втулка.m3d
  - Component [detail]: Втулка ответная  | designation М10А-00.00.003-01  | pos. 6  | Масса: 0.031838; Раздел спецификации: Детали; Форматы листов документа: A4; Примечание: Заим.; source file: D:\AquaProf\АкваProf 190\3Д модель\..\..\..\Magna\Магна Ins\Магна ins 10\М10-00.00.000\3Д\М10А-00.00.003-01 - Втулка ответная.cdw, D:\AquaProf\АкваProf 190\3Д модель\М10А-00.00.003 - Втулка ответная.m3d
  - Component [standard]: Шайба C.10.21 ГОСТ 11371-78  | qty 8  | pos. 11  | Материал: Сталь 12Х18Н10Т ГОСТ 5632-72 (density 1000 kg/m3); Масса: 0.003438; Раздел спецификации: Стандартные изделия; Рассекать на разрезах: no; additional columns: Сталь 12Х18Н10Т ГОСТ 5632-72
  - Component [standard]: Шайба 10 ГОСТ 6402-70  | qty 4  | pos. 10  | Масса: 0.00201; Раздел спецификации: Стандартные изделия; Примечание: Нерж.; Рассекать на разрезах: no; additional columns: 10; Без указания материала
  - Component [standard]: Гайка М10x1,25-6H(S16) ГОСТ 5915-70  | qty 4  | pos. 9  | Масса: 0.01022; Раздел спецификации: Стандартные изделия; Рассекать на разрезах: no; additional columns: М10x1,25-6H (S16); Сталь 12Х18Н10Т ГОСТ 5632-72
  - Component [standard]: Болт М10x1,25-6gx60 (S16) ГОСТ 7798-70  | qty 4  | pos. 8  | Масса: 0.0467; Раздел спецификации: Стандартные изделия; Рассекать на разрезах: no; additional columns: Сталь 12Х18Н10Т ГОСТ 5632-72
  - Component [detail]: Заглушка @2~25 FV PPR ф. "FV-Plast"  | qty 4  | pos. 12  | Материал: Полипропилен  ГОСТ 26996-86 (density 900 kg/m3); Масса: 0.0161976; Раздел спецификации: Прочие изделия
- Part/product: Магна Ins 10-375-3-0,75-PP-Y-E-N-K-0-0-L-0-B-0-X-R  | designation М10-00.00.000-PP-375-0,75кВт-R-EPDM
    Материал: Полипропилен  ГОСТ 26996-86 (density 900 kg/m3)
    Масса: 14.7243
  - Component [assembly]: Корпус полипропилен 375 0,75кВт  / с резьбовым переходником  | designation М10-00.20.000-PP-375-0,75кВт-R  | pos. 2  | Материал: Полипропилен  ГОСТ 26996-86 (density 900 kg/m3); Масса: 4.74348; Раздел спецификации: Сборочные единицы; Форматы листов документа: 3xA3; Примечание: @100~)3xA3@101~)3xA3
  - Component [assembly]: Вал  | designation М10-00.15.000-0,75кВт  | pos. 1  | Материал: Полипропилен  ГОСТ 26996-86 (density 900 kg/m3); Масса: 0.807009; Раздел спецификации: Сборочные единицы; Форматы листов документа: 2xA3; Примечание: @100~)2xA3
  - Component [detail]: Крышка  | designation М10-00.00.002  | pos. 4
      Материал: Полипропилен  ГОСТ 26996-86 (density 900 kg/m3)
      Масса: 0.324102
      Раздел спецификации: Детали
      Форматы листов документа: 4xA4
      Примечание: @100~)4xA4
      source file: М10-00.00.002 - Крышка.cdw, М10-00.00.002 - Крышка.m3d
  - Component [detail]: Импеллер Магна10  | designation М10-00.00.001  | pos. 3  | Масса: 0.169927; Раздел спецификации: Детали; Форматы листов документа: A3; source file: М10-00.00.001 - Импеллер Магна10.cdw, М10-00.00.001 - Импеллер Магна10.m3d
  - Component [detail]: Защитная втулка  | designation М10-00.00.003  | pos. 5  | Масса: 0.0193569; Раздел спецификации: Детали; Форматы листов документа: A4; source file: D:\Magna\Магна Ins\Магна ins 10\М10-00.00.000\3Д\М10-00.00.003 - Защитная втулка.cdw, М10-00.00.003 - Защитная втулка.m3d
  - Component [detail]: Втулка ответная  | designation М10А-00.00.003-01  | pos. 6  | Масса: 0.031838; Раздел спецификации: Детали; Форматы листов документа: A4; Примечание: Заим.; source file: D:\AquaProf\АкваProf 190\3Д модель\..\..\..\Magna\Магна Ins\Магна ins 10\М10-00.00.000\3Д\М10А-00.00.003-01 - Втулка ответная.cdw, D:\AquaProf\АкваProf 190\3Д модель\М10А-00.00.003 - Втулка ответная.m3d
  - Component [standard]: Шайба C.10.21 ГОСТ 11371-78  | qty 8  | pos. 11  | Материал: Сталь 12Х18Н10Т ГОСТ 5632-72 (density 1000 kg/m3); Масса: 0.003438; Раздел спецификации: Стандартные изделия; Рассекать на разрезах: no; additional columns: Сталь 12Х18Н10Т ГОСТ 5632-72
  - Component [standard]: Шайба 10 ГОСТ 6402-70  | qty 4  | pos. 10  | Масса: 0.00201; Раздел спецификации: Стандартные изделия; Примечание: Нерж.; Рассекать на разрезах: no; additional columns: 10; Без указания материала
  - Component [standard]: Гайка М10x1,25-6H(S16) ГОСТ 5915-70  | qty 4  | pos. 9  | Масса: 0.01022; Раздел спецификации: Стандартные изделия; Рассекать на разрезах: no; additional columns: М10x1,25-6H (S16); Сталь 12Х18Н10Т ГОСТ 5632-72
  - Component [standard]: Болт М10x1,25-6gx60 (S16) ГОСТ 7798-70  | qty 4  | pos. 8  | Масса: 0.0467; Раздел спецификации: Стандартные изделия; Рассекать на разрезах: no; additional columns: Сталь 12Х18Н10Т ГОСТ 5632-72
  - Component [detail]: Заглушка @2~25 FV PPR ф. "FV-Plast"  | qty 4  | pos. 12  | Материал: Полипропилен  ГОСТ 26996-86 (density 900 kg/m3); Масса: 0.0161976; Раздел спецификации: Прочие изделия
- Part/product: Магна Ins 10-PP-425  | designation М10-00.00.000-PP-425
    Материал: Полипропилен  ГОСТ 26996-86 (density 900 kg/m3)
    Масса: 11.5823
  - Component [assembly]: Вал  | designation М10-00.15.000-0,55кВт-425  | pos. 1
      Материал: Полипропилен  ГОСТ 26996-86 (density 900 kg/m3)
      Масса: 0.580892
      Раздел спецификации: Сборочные единицы
      Форматы листов документа: 2xA3
      Примечание: @100~)2xA3
      source file: М10-00.15.000 - Вал.a3d
  - Component [detail]: Крышка  | designation М10-00.00.002  | pos. 4
      Материал: Полипропилен  ГОСТ 26996-86 (density 900 kg/m3)
      Масса: 0.324102
      Раздел спецификации: Детали
      Форматы листов документа: 4xA4
      Примечание: @100~)4xA4
      source file: М10-00.00.002 - Крышка.cdw, М10-00.00.002 - Крышка.m3d
  - Component [detail]: Импеллер Магна10  | designation М10-00.00.001  | pos. 3  | Масса: 0.169927; Раздел спецификации: Детали; Форматы листов документа: A3; source file: М10-00.00.001 - Импеллер Магна10.cdw, М10-00.00.001 - Импеллер Магна10.m3d
  - Component [detail]: Защитная втулка  | designation М10-00.00.003  | pos. 5  | Масса: 0.0193569; Раздел спецификации: Детали; Форматы листов документа: A4; source file: D:\Magna\Магна Ins\Магна ins 10\М10-00.00.000\3Д\М10-00.00.003 - Защитная втулка.cdw, М10-00.00.003 - Защитная втулка.m3d
  - Component [detail]: Втулка ответная  | designation М10А-00.00.003-01  | pos. 6  | Масса: 0.031838; Раздел спецификации: Детали; Форматы листов документа: A4; Примечание: Заим.; source file: D:\AquaProf\АкваProf 190\3Д модель\..\..\..\Magna\Магна Ins\Магна ins 10\М10-00.00.000\3Д\М10А-00.00.003-01 - Втулка ответная.cdw, D:\AquaProf\АкваProf 190\3Д модель\М10А-00.00.003 - Втулка ответная.m3d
